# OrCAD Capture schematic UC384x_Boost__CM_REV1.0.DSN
size A3; title: UC384x_BOOST_Curent Mode; rev: 1.0
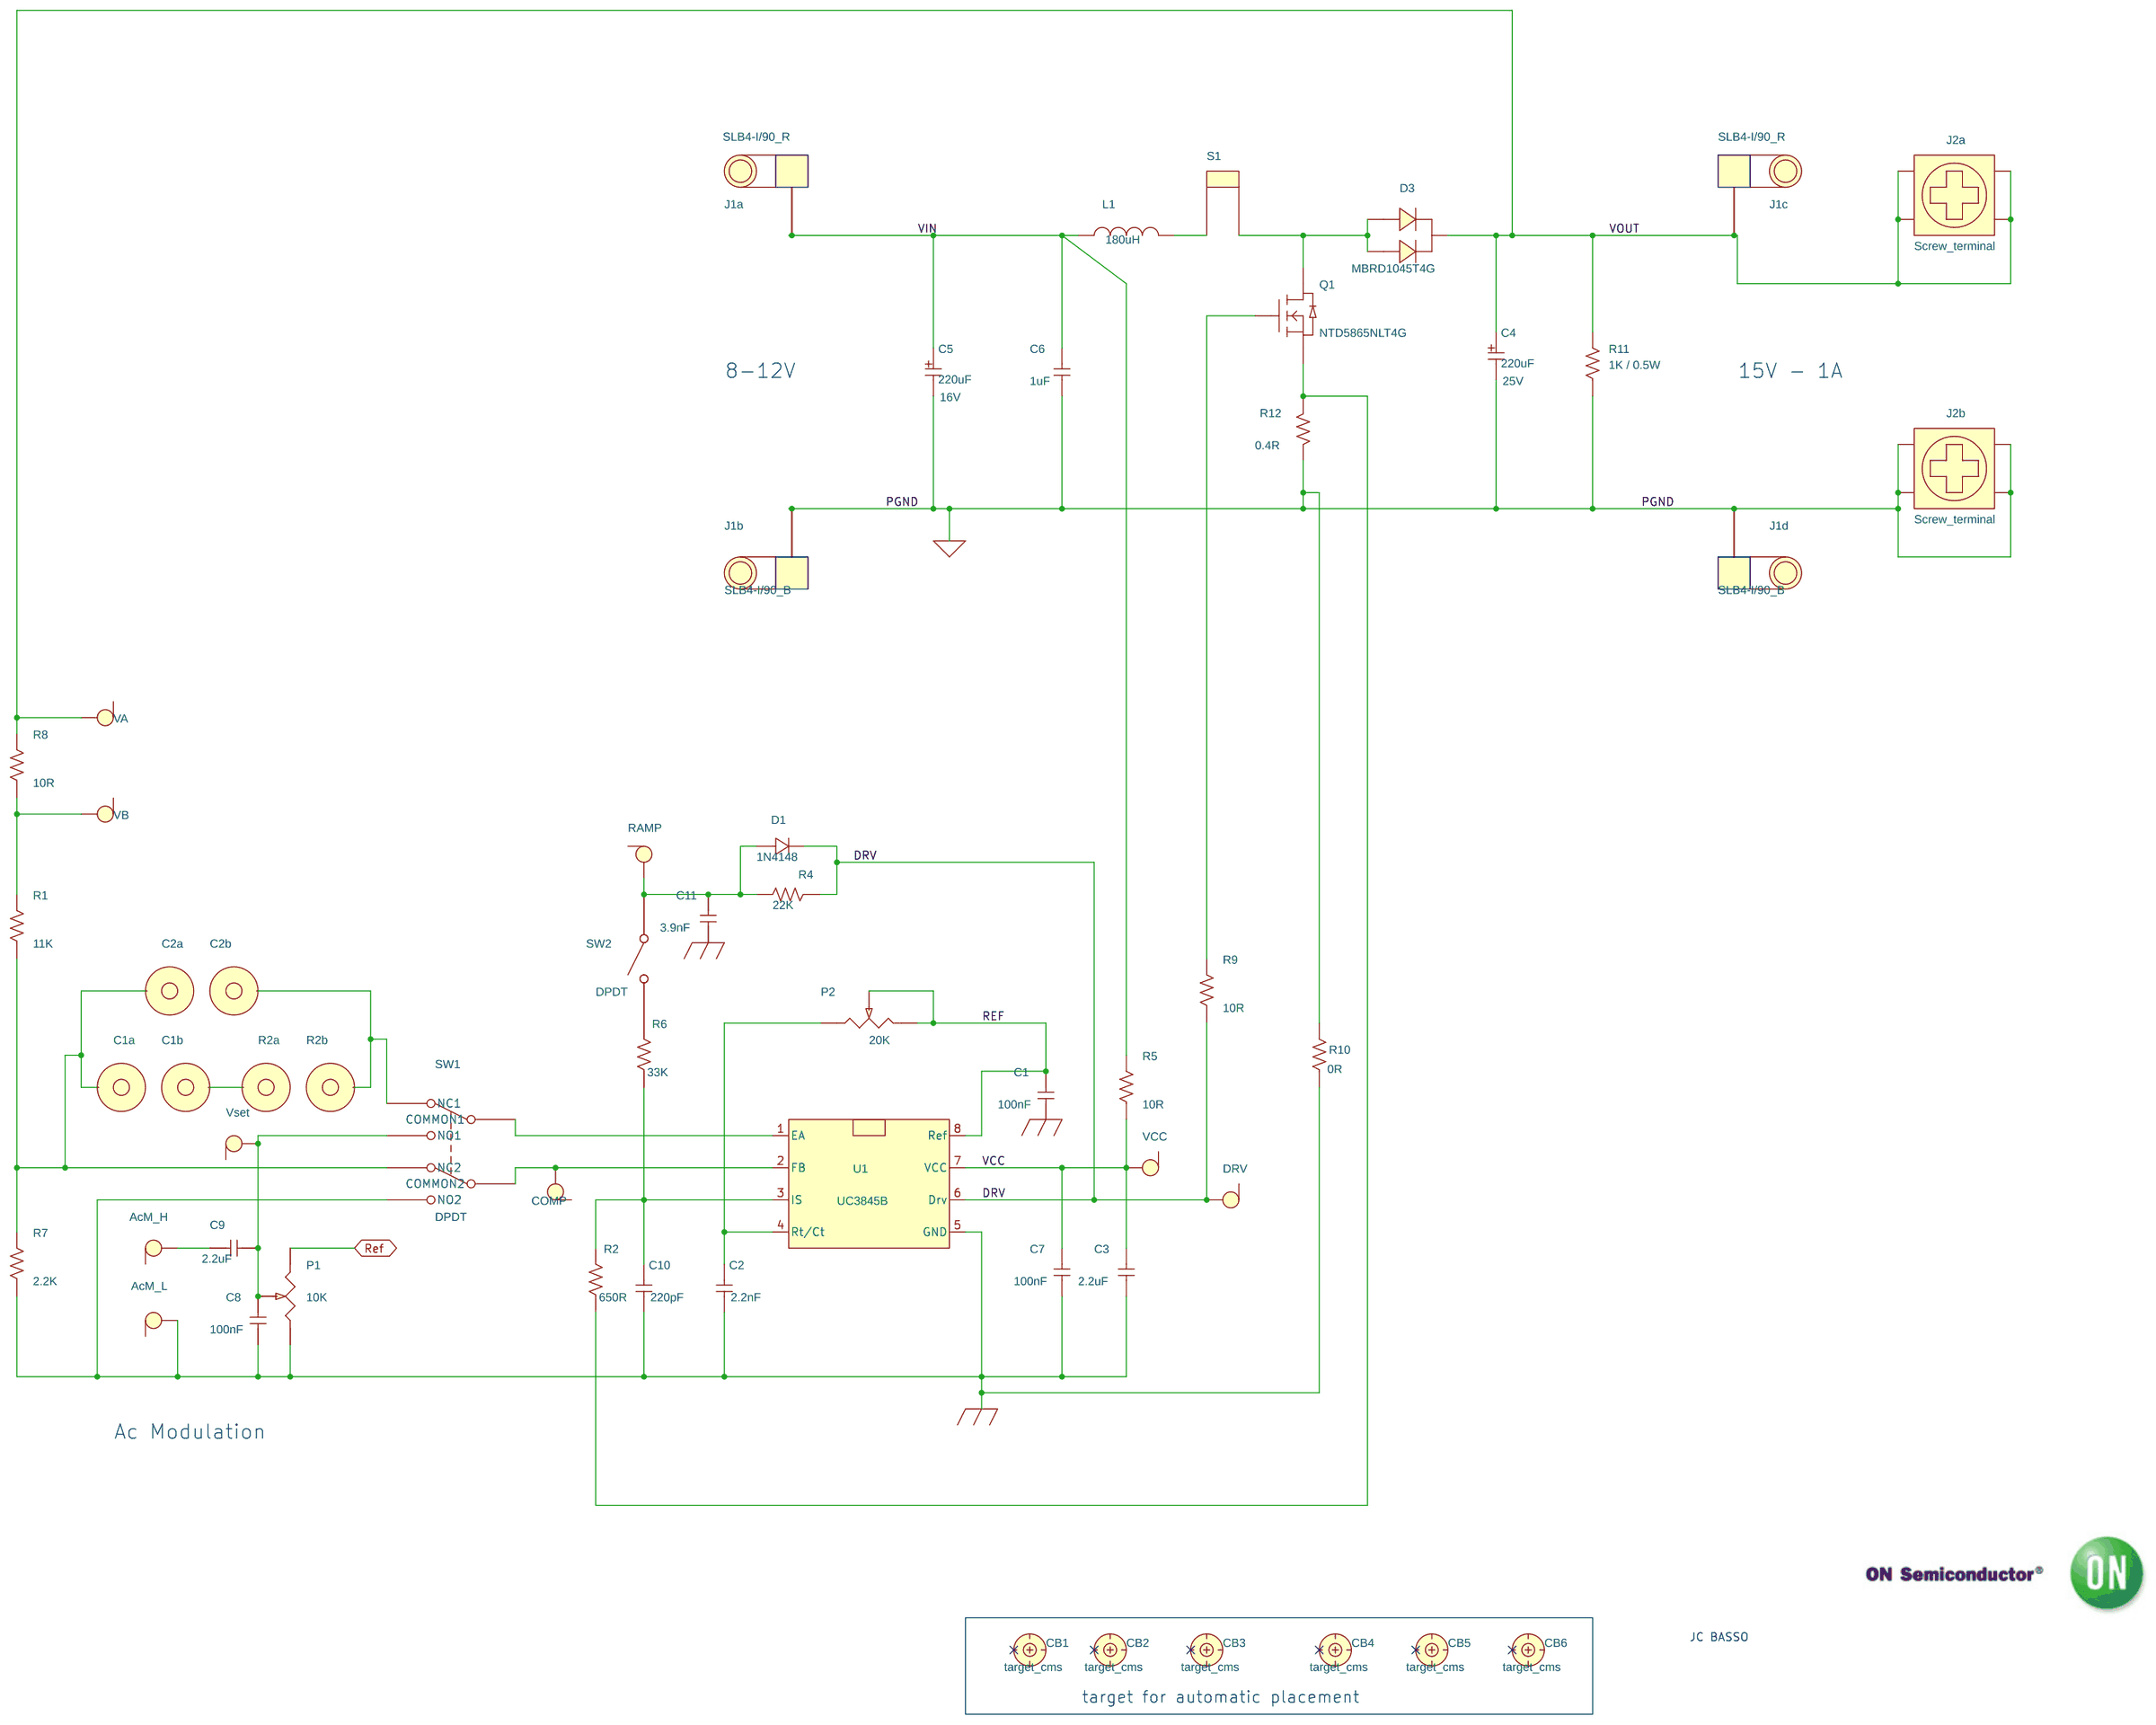
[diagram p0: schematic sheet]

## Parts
AcM_H  TEST POINT  [TP]
AcM_L  TEST POINT  [TP]
C1  100nF  [0805]
C1a  D  [PLOT_5380598-2]
C1b  D  [PLOT_5380598-2]
C2  2.2nF  [0805]
C2a  D  [PLOT_5380598-2]
C2b  D  [PLOT_5380598-2]
C3  2.2uF  [capa_ch_d5_h11_p2]
C4  220uF  [CAPA_ch_D8_H12_P3v5]
C5  220uF  [CAPA_ch_D8_H12_P3v5]
C6  1uF  [0805]
C7  100nF  [0805]
C8  100nF  [0805]
C9  2.2uF  [0805]
C10  220pF  [0805]
C11  3.9nF  [0805]
CB1  target_cms  [mire_low]
CB2  target_cms  [mire_low]
CB3  target_cms  [mire_low]
CB4  target_cms  [mire_low]
CB5  target_cms  [mire_low]
CB6  target_cms  [mire_low]
COMP  TEST POINT  [TP]
D1  1N4148  [SOD523]
D3  MBRD1045T4G  [DPAK_TO252]
DRV  TEST POINT  [TP]
J1a  SLB4-I/90_R  [BANANE_4MM_SLB4]
J1b  SLB4-I/90_B  [BANANE_4MM_SLB4]
J1c  SLB4-I/90_R  [BANANE_4MM_SLB4]
J1d  SLB4-I/90_B  [BANANE_4MM_SLB4]
J2a  Screw_terminal  [pc_7701]
J2b  Screw_terminal  [pc_7701]
L1  180uH  [SELF_MSS1210]
P1  10K  [potar_12t_3266W]
P2  20K  [potar_12t_3266W]
Q1  NTD5865NLT4G  [DPAK_TO252]
R1  11K  [0805]
R2  650R  [0805]
R2a  D  [PLOT_5380598-2]
R2b  D  [PLOT_5380598-2]
R4  22K  [0805]
R5  10R  [0805]
R6  33K  [0805]
R7  2.2K  [0805]
R8  10R  [0805]
R9  10R  [0805]
R10  0R  [1206]
R11  1K / 0.5W  [RC21U]
R12  0.4R  [RC21U]
RAMP  TEST POINT  [TP]
S1  Strap  [jumper400h]
SW1  DPDT  [sw_76SD01ST]
SW2  DPDT  [switch-1k2]
U1  UC3845B  [DIP8_sup]
VA  TEST POINT  [TP]
VB  TEST POINT  [TP]
VCC  TEST POINT  [TP]
Vset  TEST POINT  [TP]

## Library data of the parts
AcM_H AcM_L COMP DRV RAMP VA VB VCC Vset = TEST_POINT_0_v2
C1-C3 C6-C11 = C: COMPFIXED: NO; COMPGROUP: 0; COMPHEIGHT: 0.000; COMPKEY: NO; COMPLOC: [5662.500,337.500]; COMPLOCKED: NO; COMPROT: 270; COMPSIDE: BOT; DECOUPLER: NO; MEMORY: NO; VOLTAGE: 25V
C1a C1b C2a C2b R2a R2b = T_POINT_R_0
C4 = C_elect_0: PART_NUMBER: 1831278; Voltage: 25V
C5 = C_elect_0: PART_NUMBER: 1831278; Voltage: 16V
CB1-CB6 = target_cms
D1 = D1N4148: COMPFIXED: NO; COMPGROUP: 0; COMPHEIGHT: 0.000; COMPKEY: NO; COMPLOC: [2825.000,1450.000]; COMPLOCKED: NO; COMPROT: 90; COMPSIDE: TOP; DECOUPLER: NO; FPLIST: DO35 H; MEMORY: NO; PART_NUMBER: 464-198
D3 = dual_diodeAAK
J1a J1b J1c J1d = HEADER_1_0
J2a J2b = 4_HEADER_0
L1 = L: COMPFIXED: NO; COMPGROUP: 0; COMPHEIGHT: 0.000; COMPKEY: NO; COMPLOC: [6725.000,1075.000]; COMPLOCKED: NO; COMPROT: 270; COMPSIDE: TOP; DECOUPLER: NO; MEMORY: NO; PART_NUMBER: 2211721
P1 P2 = RESISTOR_VAR
Q1 = NMOS_3: PART_NUMBER: IPA50R250CP
R1 R2 R4-R9 = R: COMPFIXED: NO; COMPGROUP: 0; COMPHEIGHT: 0.000; COMPKEY: NO; COMPLOC: [1787.500,750.000]; COMPLOCKED: NO; COMPROT: 90; COMPSIDE: TOP; DECOUPLER: NO; FPLIST: AX/RC05,SM/C_1206H,AX/RC07,AX/RC07_D; MEMORY: NO; VOLTAGE: 200v
R10 = R: ALT_SYMBOLS: RES_1W_D5XL12_jp; COMPFIXED: NO; COMPGROUP: 0; COMPHEIGHT: 0.000; COMPKEY: NO; COMPLOC: [1787.500,750.000]; COMPLOCKED: NO; COMPROT: 90; COMPSIDE: TOP; DECOUPLER: NO; FPLIST: AX/RC05,SM/C_1206H,AX/RC07,AX/RC07_D; MEMORY: NO; VOLTAGE: 200v
R11 = R: COMPFIXED: NO; COMPGROUP: 0; COMPHEIGHT: 0.000; COMPKEY: NO; COMPLOC: [1787.500,750.000]; COMPLOCKED: NO; COMPROT: 90; COMPSIDE: TOP; DECOUPLER: NO; FPLIST: AX/RC05,SM/C_1206H,AX/RC07,AX/RC07_D; MEMORY: NO; PART_NUMBER: NC; VOLTAGE: 200v
R12 = R: COMPFIXED: NO; COMPGROUP: 0; COMPHEIGHT: 0.000; COMPKEY: NO; COMPLOC: [4650.000,400.000]; COMPLOCKED: NO; COMPROT: 180; COMPSIDE: TOP; DECOUPLER: NO; FPLIST: AX/RC07_D,AX/RC07,SM/C_1206H,AX/RC05; MEMORY: NO; PART_NUMBER: LVR03R0800FE12
S1 = TEST_POINT_0
SW1 = SW_DPDT_SM_0
SW2 = SW_SPST: NC: 3
U1 = UC3845B

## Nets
GND_EARTH: AcM_L.1 C1.2 C2.2 C3.2 C7.2 C8.2 C10.2 C11.2 P1.1(A) R7.1 R10.1 SW1.2(NO2) U1.5(GND)
GND_SIGNAL: C4.2(-) C5.2(-) C6.2 J1b.1 J1b.2 J1b.3 J1b.4 J1b.5 J1d.1 J1d.2 J1d.3 J1d.4 J1d.5 J2b.1 J2b.2 J2b.3 J2b.4 R10.2 R11.1 R12.2
VCC: C3.1 C7.1 R5.1 U1.7(VCC) VCC.1
VIN: C5.1(+) C6.1 J1a.1 J1a.2 J1a.3 J1a.4 J1a.5 L1.1 R5.2
DRV: D1.2 DRV.1 R4.1 R9.1 U1.6(Drv)
Ref: C1.1 P1.3(B) P2.2(WIPER) P2.3(B) U1.8(Ref)
VOUT: C4.1(+) D3.2(C) J1c.1 J1c.2 J1c.3 J1c.4 J1c.5 J2a.1 J2a.2 J2a.3 J2a.4 R8.2 R11.2 VA.1
N12290274: L1.2 S1.2
N12290314: D3.1(A1) D3.3(A2) Q1.2(d) S1.1
N12290349: Q1.3(s) R2.1 R12.1
N12292005: Q1.1(g) R9.2
N12295463: C2.1 P2.1(A) U1.4(Rt/Ct)
N12295845: C10.1 R2.2 R6.1 U1.3(IS)
N12296104: COMP.1 SW1.C2(COMMON2) U1.2(FB)
N12296108: SW1.C1(COMMON1) U1.1(EA)
N12296437: C11.1 D1.1 R4.2 RAMP.1 SW2.1
N12297349: R1.2 R8.1 VB.1
N12298127: C1a.1(TP) C2a.1(TP) R1.1 R7.2 SW1.22(NC2)
N12298463: C8.1 C9.2 P1.2(WIPER) SW1.1(NO1) Vset.1
N12299817: C1b.1(TP) R2a.1(TP)
N12299821: C2b.1(TP) R2b.1(TP) SW1.11(NC1)
N12301916: AcM_H.1 C9.1
N12517103: R6.2 SW2.2

Not connected (* = marked no-connect by the designer): CB1 1*; CB2 1*; CB3 1*; CB4 1*; CB5 1*; CB6 1*

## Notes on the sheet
- 8-12V
- 15V - 1A
- Ac Modulation
- JC BASSO
- target for automatic placement
